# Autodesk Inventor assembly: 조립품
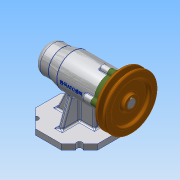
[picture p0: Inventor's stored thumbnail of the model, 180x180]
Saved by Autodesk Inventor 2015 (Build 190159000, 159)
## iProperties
Created: 2019-12
Part Number: 조립품
Document SubType Name: Assembly
Designer: user
Author: user
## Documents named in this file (12)
- C:\Users\user\Desktop\491204V1063\조립품.iam
- C:\Users\user\Desktop\491204V1063\본체.ipt
- C:\Users\user\Desktop\491204V1063\커버.ipt
- C:\Users\user\Desktop\491204V1063\오일 실.ipt
- C:\Users\user\Desktop\491204V1063\베어링 6004.ipt
- C:\Users\user\Desktop\491204V1063\축.ipt
- C:\Users\user\Desktop\491204V1063\키 5 x 5 x 16.ipt
- C:\Users\user\Desktop\491204V1063\V벨트풀리.ipt
- C:\Users\user\Desktop\491204V1063\멈춤나사 M3.ipt
- C:\Users\user\Desktop\491204V1063\어댑터슬리브.ipt
- C:\Users\user\Desktop\491204V1063\볼트 M4.ipt
- C:\Users\user\Desktop\491204V1063\베어링 51202.ipt
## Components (1 placed, 1 different names)
1. V벨트풀리:1
